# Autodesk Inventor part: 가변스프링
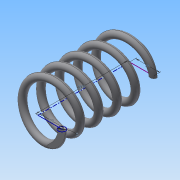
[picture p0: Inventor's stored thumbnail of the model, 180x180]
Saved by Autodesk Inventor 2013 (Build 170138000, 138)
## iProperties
Created: 2019-10
Part Number: 가변스프링
Material: 일반
Document SubType Name: Modeling
Designer: Administrator
Density: 1 g/cm^3
Mass: 18.293 g
Surface Area: 124.166 cm^2
Volume: 18.293 cm^3
Author: Administrator
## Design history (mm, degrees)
sketch "스케치1"
  geometry: L1 (0, 0)-(21, 0); L2 (0, 0)-(0, 67.25); L3 (0, 67.25)-(21, 67.25); C1 r 3 at (21, 0)
  constraints: 6 end point, 2 perpendicular, 1 centre point, 1 coincident, 1 horizontal
  dimensions: "d0" = 21 distance of L1.start L1.end; "d1" = 67.25 distance of L1.start L2.end (derived); "d2" = 21 distance of L2.end L3.end; "d3" = 6 diameter of C1
feature "코일1" pitch "d4" = 10; turns "d6" = 5; dims "d5" = 67.25 (= d1), "d7" = 0, angle "d8" = 90 deg, angle "d9" = 90 deg, "d10" = 0, "d11" = 0
sketch "스케치2"
  geometry: L1 (67.25, 25)-(0, 25); L2 (0, 25)-(0, -25); L3 (0, -25)-(67.25, -25); L4 (67.25, -25)-(67.25, 25); 2 further points
  constraints: 8 end point, 2 parallel, 1 coincident, 1 horizontal, 1 midpoint, 1 perpendicular
  dimensions: "d12" = 50 distance of L3.end L1.start; "d14" = 67.25 distance of L2.end L3.end (= d1)
extrude "돌출1" sketch "스케치2" stored distance "d15" = 0; taper "d16" = 0 deg
node "솔리드1"
